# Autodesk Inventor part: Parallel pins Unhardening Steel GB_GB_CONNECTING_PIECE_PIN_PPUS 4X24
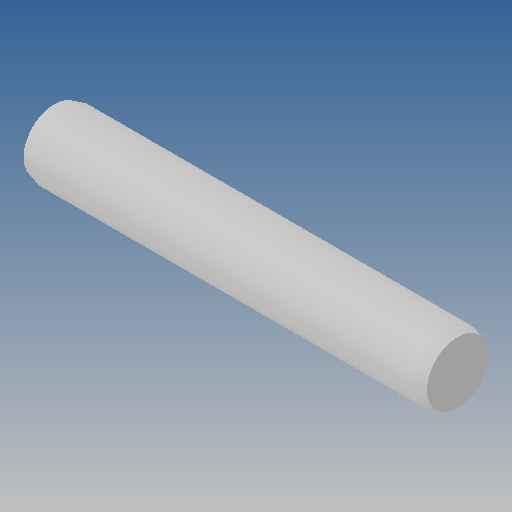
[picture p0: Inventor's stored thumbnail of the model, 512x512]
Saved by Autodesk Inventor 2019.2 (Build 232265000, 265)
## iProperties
Created: 2013-09
Part Number: Parallel pins Unhardening Steel GB_GB_CONNECTING_PIECE_PIN_PPUS 4X24
Material: Ogólny
Document SubType Name: Modeling
Designer: CADENGINEERING4
Density: 1 g/cm^3
Appearance: Domyślna
Author: CADENGINEERING4
Revision Number: ÈÎºÎ
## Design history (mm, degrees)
feature "Base-Revolve"
node "Bryła1"
